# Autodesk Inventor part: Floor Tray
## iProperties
Shininess: 92.0
Angle Display Precision: 2
Document Length Units: 11269
Document Angle Units: 11279
Document Time Units: 11290
Document Mass Units: 11283
Document Length Units Precision: 3
Document Angle Units Precision: 2
Compacted: True
Created: 2001-08
Part Number: Floor Tray
Document SubType Name: Sheet Metal
Designer: Martin Budgell
Density: 0.0
Volumn: 0.0
Area: 0.0
PropertySet Name: Model Information
Control State: 0
Master: False
Checked Out: False
Author: Martin Budgell
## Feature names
1. Corner Round1
2. Hole1
3. Corner Round2
4. Corner Round3
5. Hole3
6. Plate1
7. Plate2
8. Bend1
9. Plate3
10. Bend2
11. Cut1
12. Cut2
13. Cut4
14. Cut5
